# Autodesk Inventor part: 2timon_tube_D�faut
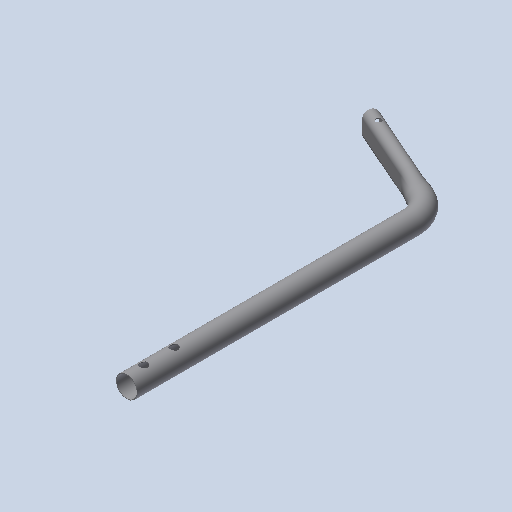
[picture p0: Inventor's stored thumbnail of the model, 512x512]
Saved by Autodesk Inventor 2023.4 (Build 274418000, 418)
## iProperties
Created: 2011-01
Part Number: 2timon_tube_D�faut
Document SubType Name: Modeling
Designer: eric
Density: 1 g/cm^3
Mass: 59.322 g
Surface Area: 1189.44 cm^2
Volume: 59.322 cm^3
Material: Générique
Appearance: Par défaut
Author: eric
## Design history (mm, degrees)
feature "Base1"
node "Corps solides"
node "Corps surfaciques"
node "Solide1"
